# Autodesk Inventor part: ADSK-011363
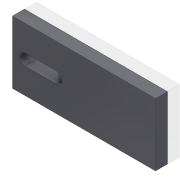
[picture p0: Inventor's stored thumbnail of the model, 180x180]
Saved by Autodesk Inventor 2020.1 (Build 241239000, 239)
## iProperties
Created: 1999-12
Part Number: ADSK-011363
Material: Acier doux
Document SubType Name: Modeling
Designer: sspink
Density: 7.86 g/cm^3
Appearance: Metal-Steel(Polish)
Mass: 405.131 g
Surface Area: 146.925 cm^2
Volume: 51.5434 cm^3
Control State: 0
Checked Out: False
Master: False
Shininess: 0.0
Length Units: 11269
Angle Units: 11279
Time Units: 11290
Mass Units: 11283
Length Display Precision: 3
Angle Display Precision: 2
Compacted: True
CUTLENGTH: 4.5
MATERIAL DESC: FLAT,HRS,0.38 X 2.00
MATERIAL_NUMBER: A084406
Dimensions: 114x50x9,5 mm
Mass: 0,405 kg
DocNumber: ADSK-011363.ipt
Folder: 01 - Themengebiete\Simplification\01 - Packaging machine\
VDS_Category: 3D Komponenten
Density: 0.0
Volumn: 0.0
Area: 0.0
PropertySet Name: Model Information
Author: sspink
Revision Number: -
Title: fixing plate
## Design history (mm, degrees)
node "Solide1"
  node "Extrusion1" dims "d2" = 9.525, "d3" = 0
  node "Extrusion2" dims "d8" = 6.35, "d9" = 0
sketch "Sketch1"
  geometry: L1 (-57, -25)-(57, -25); L2 (57, -25)-(57, 25); L3 (57, 25)-(-57, 25); L4 (-57, 25)-(-57, -25); 3 further points
  constraints: 8 end point, 2 midpoint, 2 parallel, 1 horizontal, 1 horizontal alignment, 1 perpendicular, 1 vertical alignment
  dimensions: "d0" = 50 distance of L3.end L1.start; "d1" = 114 distance of L1.start L1.end
sketch "Sketch2"
  geometry: L1 (-22, -4.5)-(-47, -4.5); L2 (-47, -4.5)-(-47, 4.5); L3 (-47, 4.5)-(-22, 4.5); L4 (-22, 4.5)-(-22, -4.5); L5 (-57, -25)-(-57, 25) reference; A1 r 4.5 centre (-47, 0) between (-47, 4.5) and (-47, -4.5); A2 r 4.5 centre (-22, 0) between (-22, -4.5) and (-22, 4.5); 2 further points
  constraints: 8 end point, 4 point on circle, 2 centre point, 2 midpoint, 2 parallel, 2 tangent, 1 horizontal, 1 horizontal alignment, 1 perpendicular
  dimensions: "d10" = 9 distance between parallel lines of L1 L3; "d11" = 10 distance from line of L5 A1.centre; "d12" = 25 distance of L2.end L3.end
node "Corps solides"
node "Corps surfaciques"
